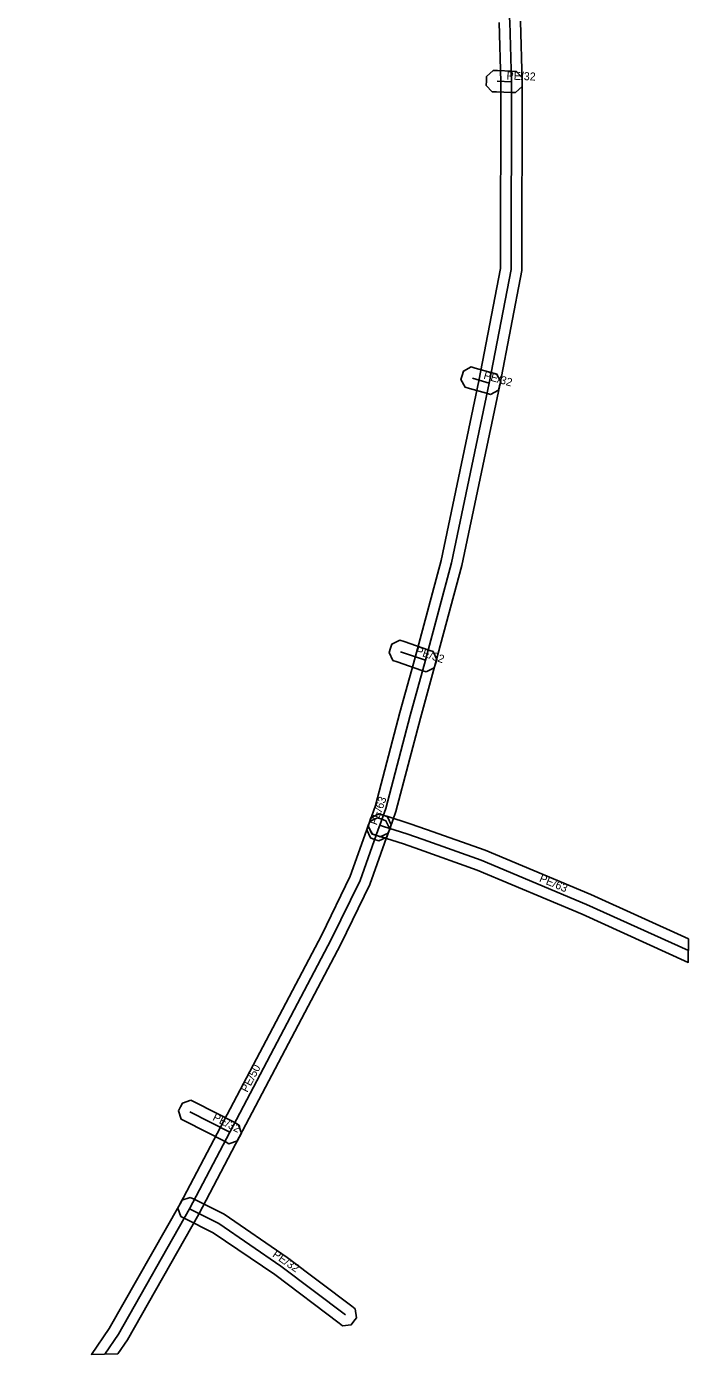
# Model space of a CAD drawing. Extents: x -682697 to -681888, y -1059966 to -1059631.
# Drawn here: x -681951.1 to -681889.1, y -1059951.4 to -1059827 of the extents above; entities that cross this region are included whole.
import ezdxf

# ---------------------------------------------------------------- set-up
doc = ezdxf.new("R2010")
doc.units = 0
for name, color, linetype in [('1', 7, 'Continuous'), ('24', 7, 'Continuous'), ('30', 7, 'Continuous')]:
    doc.layers.add(name, color=color, linetype=linetype)

msp = doc.modelspace()

# ---------------------------------------------------------------- linework, layer by layer
at = {"layer": '1'}
msp.add_lwpolyline([(-681904.79, -1059826.48), (-681904.64, -1059832.15), (-681904.69, -1059849.84), (-681906.75, -1059860.58), (-681910.3, -1059877.46), (-681912.76, -1059886.61), (-681914.18, -1059891.77), (-681916.48, -1059900.53), (-681917.06, -1059902.15), (-681917.2, -1059902.54), (-681917.95, -1059902.89), (-681918.34, -1059902.75), (-681918.73, -1059902.61), (-681919.08, -1059901.86), (-681918.94, -1059901.47), (-681918.4, -1059899.95), (-681916.12, -1059891.25), (-681914.69, -1059886.09), (-681912.24, -1059877), (-681908.71, -1059860.18), (-681906.69, -1059849.64), (-681906.64, -1059832.17), (-681906.79, -1059826.6)], dxfattribs=at)
for points in [[(-681905.26, -1059833.17), (-681905.68, -1059833.16), (-681907.04, -1059833.11), (-681907.45, -1059833.09), (-681908.01, -1059832.49), (-681908, -1059832.07), (-681907.98, -1059831.66), (-681907.38, -1059831.1), (-681906.96, -1059831.11), (-681905.6, -1059831.16), (-681905.19, -1059831.18), (-681904.63, -1059831.78), (-681904.64, -1059832.2), (-681904.66, -1059832.61)], [(-681907.61, -1059861.46), (-681908, -1059861.34), (-681909.58, -1059860.89), (-681909.98, -1059860.78), (-681910.39, -1059860.05), (-681910.27, -1059859.66), (-681910.16, -1059859.26), (-681909.43, -1059858.85), (-681909.04, -1059858.97), (-681907.46, -1059859.42), (-681907.06, -1059859.53), (-681906.66, -1059860.26), (-681906.77, -1059860.65), (-681906.88, -1059861.05)], [(-681913.65, -1059887.43), (-681914.05, -1059887.3), (-681916.38, -1059886.5), (-681916.77, -1059886.36), (-681917.13, -1059885.62), (-681917, -1059885.23), (-681916.86, -1059884.83), (-681916.12, -1059884.47), (-681915.72, -1059884.6), (-681913.4, -1059885.4), (-681913, -1059885.54), (-681912.64, -1059886.28), (-681912.77, -1059886.68), (-681912.91, -1059887.07)], [(-681941.66, -1059950.02), (-681942.56, -1059951.32), (-681945.03, -1059951.39), (-681943.36, -1059948.96), (-681936.72, -1059937.27), (-681932.94, -1059930.09), (-681923.43, -1059912.06), (-681920.76, -1059906.58), (-681919.08, -1059901.85), (-681918.94, -1059901.47), (-681918.2, -1059901.11), (-681917.81, -1059901.25), (-681917.42, -1059901.39), (-681917.06, -1059902.14), (-681917.2, -1059902.52), (-681918.92, -1059907.36), (-681921.65, -1059912.96), (-681931.17, -1059931.02), (-681934.96, -1059938.23)], [(-681916.92, -1059901.77), (-681917.06, -1059902.16), (-681917.2, -1059902.54), (-681917.34, -1059902.93), (-681918.1, -1059903.27), (-681918.49, -1059903.13), (-681918.88, -1059902.99), (-681919.22, -1059902.23), (-681919.08, -1059901.84), (-681918.94, -1059901.46), (-681918.8, -1059901.07), (-681918.04, -1059900.73), (-681917.65, -1059900.87), (-681917.27, -1059901.02)], [(-681889.05, -1059912.46), (-681889.07, -1059914.65), (-681899.02, -1059910.14), (-681908.85, -1059906), (-681914.27, -1059904.08), (-681915.77, -1059903.56), (-681917.95, -1059902.87), (-681918.3, -1059902.76), (-681918.69, -1059902.64), (-681919.08, -1059901.91), (-681918.95, -1059901.51), (-681918.83, -1059901.12), (-681918.1, -1059900.73), (-681917.7, -1059900.86), (-681917.35, -1059900.97), (-681915.14, -1059901.66), (-681913.61, -1059902.2), (-681908.13, -1059904.14), (-681898.22, -1059908.3)], [(-681935.71, -1059927.57), (-681935.35, -1059927.76), (-681931.6, -1059929.67), (-681931.23, -1059929.86), (-681930.97, -1059930.64), (-681931.16, -1059931.01), (-681931.35, -1059931.38), (-681932.14, -1059931.64), (-681932.51, -1059931.45), (-681936.25, -1059929.54), (-681936.62, -1059929.35), (-681936.88, -1059928.56), (-681936.69, -1059928.2), (-681936.5, -1059927.83)], [(-681935.77, -1059936.67), (-681935.4, -1059936.85), (-681932.59, -1059938.25), (-681926.69, -1059942.29), (-681920.62, -1059946.87), (-681920.29, -1059947.12), (-681920.17, -1059947.94), (-681920.42, -1059948.27), (-681920.67, -1059948.6), (-681921.49, -1059948.72), (-681921.82, -1059948.47), (-681927.85, -1059943.91), (-681933.61, -1059939.98), (-681936.29, -1059938.65), (-681936.66, -1059938.46), (-681936.92, -1059937.68), (-681936.74, -1059937.3), (-681936.55, -1059936.93)]]:
    msp.add_lwpolyline(points, close=True, dxfattribs=at)
at = {"layer": '24'}
for points in [[(-681951.12, -1059753.66), (-681946.39, -1059758.1), (-681942.72, -1059761.75), (-681938.13, -1059766.31), (-681931.96, -1059775.58), (-681929.01, -1059780.07), (-681919.67, -1059796.12), (-681917.11, -1059800.91), (-681917.06, -1059801.01), (-681914.01, -1059806.65), (-681912.54, -1059809.4), (-681910.97, -1059812.27), (-681908.88, -1059816.07), (-681907.31, -1059818.96), (-681906.12, -1059822.85), (-681905.79, -1059826.54), (-681905.64, -1059832.16), (-681905.69, -1059849.74), (-681907.73, -1059860.38), (-681911.27, -1059877.23), (-681913.72, -1059886.35), (-681915.15, -1059891.51), (-681917.44, -1059900.24), (-681918, -1059901.81)], [(-681905.64, -1059832.16), (-681907, -1059832.11)], [(-681907.73, -1059860.38), (-681909.31, -1059859.93)], [(-681913.72, -1059886.35), (-681916.05, -1059885.55)], [(-681918, -1059901.81), (-681918.14, -1059902.19)], [(-681918, -1059901.81), (-681917.65, -1059901.92), (-681915.45, -1059902.61), (-681913.94, -1059903.14), (-681908.49, -1059905.07), (-681898.62, -1059909.22), (-681889.06, -1059913.55)], [(-681943.79, -1059951.35), (-681942.51, -1059949.49), (-681935.84, -1059937.75), (-681932.05, -1059930.56), (-681922.54, -1059912.51), (-681919.84, -1059906.97), (-681918.14, -1059902.19)], [(-681935.8, -1059928.65), (-681932.05, -1059930.56)], [(-681935.84, -1059937.75), (-681933.1, -1059939.11), (-681927.27, -1059943.1), (-681921.22, -1059947.67)]]:
    msp.add_lwpolyline(points, dxfattribs=at)

# ---------------------------------------------------------------- texts
at = {"layer": '30'}
for s, rotation, p in [('PE/32', 357.8945, (-681906.12, -1059831.94)), ('PE/32', 344.1025, (-681908.32, -1059859.96)), ('PE/32', 341.0502, (-681914.69, -1059885.75)), ('PE/63', 69.7751, (-681918.29, -1059901.85)), ('PE/63', 337.1949, (-681903.1, -1059907.05)), ('PE/50', 62.2128, (-681930.42, -1059926.89)), ('PE/32', 333.0147, (-681933.73, -1059929.4)), ('PE/32', 325.6126, (-681928.12, -1059942.18))]:
    msp.add_text(s, height=0.75, rotation=rotation, dxfattribs=at).set_placement(p)

doc.saveas('drawing.dxf')
